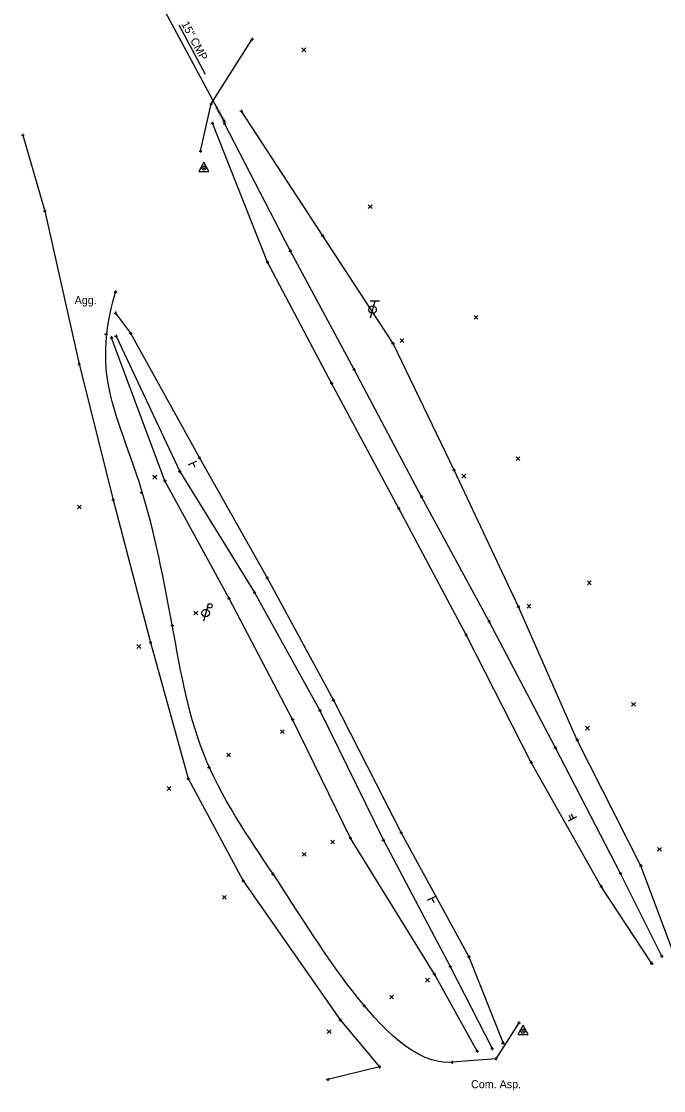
# Model space of a CAD drawing. Extents: x 2298098 to 2302860, y 557788 to 564251.
# Drawn here: x 2299513.3 to 2299738, y 561246.9 to 561620.8 of the extents above; entities that cross this region are included whole.
import ezdxf

# ---------------------------------------------------------------- set-up
doc = ezdxf.new("R2010")
doc.units = 0
for name, color, linetype in [('DR_X_Ditch', 7, 'Continuous'), ('DR_X_Elev_Flow', 7, 'Continuous'), ('DR_X_Storm_Sewer', 7, 'Continuous'), ('DR_X_Text', 7, 'Continuous'), ('PV_X_Driveway', 7, 'Continuous'), ('PV_X_Text', 7, 'Continuous'), ('SC_Scratch1', 7, 'Continuous'), ('SN_X_Public', 7, 'Continuous'), ('SV_P_Aerial_Targets', 7, 'Continuous'), ('SV_X_Break_Lines', 7, 'Continuous'), ('SV_X_Random_Point', 7, 'Continuous'), ('SV_X_Shot_Marker', 7, 'Continuous'), ('UT_X_Electric_Cells', 7, 'Continuous'), ('UT_X_Telecom_Cells', 7, 'Continuous')]:
    doc.layers.add(name, color=color, linetype=linetype)

msp = doc.modelspace()

# ---------------------------------------------------------------- linework, layer by layer
at = {"layer": 'DR_X_Ditch'}
for points in [[(2299737.31, 561293.86), (2299722.87, 561322.84), (2299700.1, 561366.76), (2299676.94, 561410.9), (2299653.32, 561454.59), (2299629.71, 561499.05), (2299607.4, 561540.48), (2299584.35, 561585.15)], [(2299546.42, 561510.69), (2299568.71, 561463.43), (2299594.86, 561421.07), (2299617.75, 561379.83), (2299639.94, 561334.43), (2299663.33, 561290.25), (2299678, 561261.57)]]:
    msp.add_lwpolyline(points, dxfattribs=at)
at = {"layer": 'DR_X_Elev_Flow'}
for p, q in [((2299583.77, 561585.83), (2299584.77, 561585.83)), ((2299584.27, 561586.33), (2299584.27, 561585.33)), ((2299584.27, 561585.83), (2299584.27, 561585.83))]:
    msp.add_line(p, q, dxfattribs=at)
at = {"layer": 'DR_X_Storm_Sewer'}
msp.add_line((2299556.47, 561637.55), (2299584.27, 561585.83), dxfattribs=at)
at = {"layer": 'DR_X_Text'}
msp.add_line((2299577.72, 561602.29), (2299568.48, 561619.48), dxfattribs=at)
at = {"layer": 'PV_X_Driveway'}
for p, q in [((2299687.34, 561270.58), (2299679.27, 561258.05)), ((2299679.27, 561258.05), (2299663.94, 561256.81))]:
    msp.add_line(p, q, dxfattribs=at)
for points in [[(2299575.95, 561575.41), (2299579.72, 561591.96), (2299594.02, 561614.57)], [(2299513.82, 561581.04), (2299521.51, 561554.48), (2299533.54, 561500.96), (2299545.43, 561453.46), (2299558.48, 561403.61), (2299571.66, 561356), (2299590.93, 561320.27), (2299624.87, 561271.61), (2299638.56, 561255.18), (2299620.47, 561250.79)]]:
    msp.add_lwpolyline(points, dxfattribs=at)
msp.add_open_spline([(2299663.94, 561256.81), (2299651.33, 561255.78), (2299626.4, 561282.53), (2299604.55, 561318.9), (2299574.6, 561360.95), (2299566.43, 561408.72), (2299556.71, 561458.84), (2299538.76, 561497.94), (2299544.69, 561521.26), (2299546.28, 561526.19)], degree=3, dxfattribs=at)
at = {"layer": 'SN_X_Public'}
for p, q in [((2299571.81, 561465.72), (2299574.66, 561467.17)), ((2299573.24, 561466.45), (2299573.96, 561465.02)), ((2299707.44, 561342.62), (2299704.61, 561341.13)), ((2299705.6, 561341.65), (2299704.86, 561343.07)), ((2299706.45, 561342.1), (2299705.71, 561343.51)), ((2299706.03, 561341.88), (2299706.03, 561341.88)), ((2299655.4, 561313.48), (2299658.29, 561314.85)), ((2299656.84, 561314.17), (2299657.53, 561312.72))]:
    msp.add_line(p, q, dxfattribs=at)
at = {"layer": 'SV_P_Aerial_Targets'}
for points in [[(2299575.34, 561568.34), (2299578.94, 561568.34), (2299577.14, 561571.56)], [(2299686.98, 561266.52), (2299690.58, 561266.52), (2299688.78, 561269.74)]]:
    msp.add_lwpolyline(points, close=True, dxfattribs=at)
for centre, radius in [((2299577.14, 561569.49), 0.7), ((2299577.14, 561569.49), 0.16), ((2299688.78, 561267.68), 0.7), ((2299688.78, 561267.68), 0.16)]:
    msp.add_circle(centre, radius, dxfattribs=at)
at = {"layer": 'SV_X_Break_Lines'}
for points in [[(2299742.16, 561293.21), (2299730.03, 561325.53), (2299707.75, 561369.5), (2299687.14, 561416.12), (2299664.66, 561463.85), (2299643.3, 561508.16), (2299618.73, 561545.83), (2299590.25, 561589.38)], [(2299733.8, 561291.39), (2299716.16, 561318.33), (2299691.63, 561361.68), (2299668.9, 561406.25), (2299645.33, 561450.44), (2299621.83, 561494.34), (2299599.4, 561536.58), (2299580.12, 561585.2)], [(2299546.23, 561518.82), (2299551.51, 561511.74), (2299575.58, 561468.14), (2299599.3, 561426.17), (2299622.44, 561383.41), (2299646.14, 561337.05), (2299669.87, 561293.72), (2299681.8, 561263.53)], [(2299672.78, 561260.7), (2299657.77, 561287.57), (2299628.41, 561335.16), (2299608.18, 561376.64), (2299585.94, 561418.99), (2299563.52, 561460.16), (2299544.89, 561510.17)]]:
    msp.add_lwpolyline(points, dxfattribs=at)
at = {"layer": 'SV_X_Random_Point'}
for p, q in [((2299611.44, 561610.2), (2299612.77, 561611.53)), ((2299611.44, 561611.53), (2299612.77, 561610.2)), ((2299634.62, 561555.36), (2299635.96, 561556.7)), ((2299634.62, 561556.7), (2299635.96, 561555.36)), ((2299671.63, 561516.67), (2299672.96, 561518.01)), ((2299671.63, 561518.01), (2299672.96, 561516.67)), ((2299645.8, 561508.48), (2299647.13, 561509.82)), ((2299645.8, 561509.82), (2299647.13, 561508.48)), ((2299686.38, 561467.2), (2299687.71, 561468.54)), ((2299686.38, 561468.54), (2299687.71, 561467.2)), ((2299559.32, 561460.75), (2299560.65, 561462.09)), ((2299559.32, 561462.09), (2299560.65, 561460.75)), ((2299559.32, 561460.72), (2299560.65, 561462.05)), ((2299559.32, 561462.05), (2299560.65, 561460.72)), ((2299667.42, 561461.11), (2299668.75, 561462.45)), ((2299667.42, 561462.45), (2299668.75, 561461.11)), ((2299532.94, 561450.33), (2299534.27, 561451.66)), ((2299532.94, 561451.66), (2299534.27, 561450.33)), ((2299711.29, 561423.79), (2299712.63, 561425.12)), ((2299711.29, 561425.12), (2299712.63, 561423.79)), ((2299690.22, 561415.61), (2299691.55, 561416.95)), ((2299690.22, 561416.95), (2299691.55, 561415.61)), ((2299573.65, 561413.23), (2299574.98, 561414.56)), ((2299573.65, 561414.56), (2299574.98, 561413.23)), ((2299553.75, 561401.53), (2299555.08, 561402.86)), ((2299553.75, 561402.86), (2299555.08, 561401.53)), ((2299726.77, 561381.31), (2299728.1, 561382.64)), ((2299726.77, 561382.64), (2299728.1, 561381.31)), ((2299710.65, 561372.95), (2299711.98, 561374.29)), ((2299710.65, 561374.29), (2299711.98, 561372.95)), ((2299603.92, 561371.77), (2299605.25, 561373.1)), ((2299603.92, 561373.1), (2299605.25, 561371.77)), ((2299585.15, 561363.56), (2299586.48, 561364.9)), ((2299585.15, 561364.9), (2299586.48, 561363.56)), ((2299564.29, 561351.9), (2299565.62, 561353.23)), ((2299564.29, 561353.23), (2299565.62, 561351.9)), ((2299621.56, 561333.17), (2299622.89, 561334.5)), ((2299621.56, 561334.5), (2299622.89, 561333.17)), ((2299611.57, 561328.85), (2299612.9, 561330.18)), ((2299611.57, 561330.18), (2299612.9, 561328.85)), ((2299735.84, 561330.61), (2299737.17, 561331.95)), ((2299735.84, 561331.95), (2299737.17, 561330.61)), ((2299583.63, 561313.83), (2299584.97, 561315.17)), ((2299583.63, 561315.17), (2299584.97, 561313.83)), ((2299654.72, 561284.84), (2299656.05, 561286.17)), ((2299654.72, 561286.17), (2299656.05, 561284.84)), ((2299642.2, 561278.98), (2299643.53, 561280.31)), ((2299642.2, 561280.31), (2299643.53, 561278.98)), ((2299620.28, 561266.81), (2299621.62, 561268.15)), ((2299620.28, 561268.15), (2299621.62, 561266.81))]:
    msp.add_line(p, q, dxfattribs=at)
at = {"layer": 'SV_X_Shot_Marker'}
for p, q in [((2299593.52, 561614.57), (2299594.52, 561614.57)), ((2299594.02, 561615.07), (2299594.02, 561614.07)), ((2299594.02, 561614.57), (2299594.02, 561614.57)), ((2299579.22, 561591.96), (2299580.22, 561591.96)), ((2299579.72, 561592.46), (2299579.72, 561591.46)), ((2299579.72, 561591.96), (2299579.72, 561591.96)), ((2299589.75, 561589.38), (2299590.75, 561589.38)), ((2299590.25, 561589.88), (2299590.25, 561588.88)), ((2299590.25, 561589.38), (2299590.25, 561589.38)), ((2299579.62, 561585.2), (2299580.62, 561585.2)), ((2299580.12, 561585.7), (2299580.12, 561584.7)), ((2299580.12, 561585.2), (2299580.12, 561585.2)), ((2299583.85, 561585.15), (2299584.85, 561585.15)), ((2299584.35, 561585.65), (2299584.35, 561584.65)), ((2299584.35, 561585.15), (2299584.35, 561585.15)), ((2299513.32, 561581.04), (2299514.32, 561581.04)), ((2299513.82, 561581.54), (2299513.82, 561580.54)), ((2299513.82, 561581.04), (2299513.82, 561581.04)), ((2299575.95, 561575.91), (2299575.95, 561574.91)), ((2299575.45, 561575.41), (2299576.45, 561575.41)), ((2299575.95, 561575.41), (2299575.95, 561575.41)), ((2299521.01, 561554.48), (2299522.01, 561554.48)), ((2299521.51, 561554.98), (2299521.51, 561553.98)), ((2299521.51, 561554.48), (2299521.51, 561554.48)), ((2299618.23, 561545.83), (2299619.23, 561545.83)), ((2299618.73, 561546.33), (2299618.73, 561545.33)), ((2299618.73, 561545.83), (2299618.73, 561545.83)), ((2299606.9, 561540.48), (2299607.9, 561540.48)), ((2299607.4, 561540.98), (2299607.4, 561539.98)), ((2299607.4, 561540.48), (2299607.4, 561540.48)), ((2299598.9, 561536.58), (2299599.9, 561536.58)), ((2299599.4, 561537.08), (2299599.4, 561536.08)), ((2299599.4, 561536.58), (2299599.4, 561536.58)), ((2299545.78, 561526.19), (2299546.78, 561526.19)), ((2299546.28, 561526.69), (2299546.28, 561525.69)), ((2299546.28, 561526.19), (2299546.28, 561526.19)), ((2299545.73, 561518.82), (2299546.73, 561518.82)), ((2299546.23, 561519.32), (2299546.23, 561518.32)), ((2299546.23, 561518.82), (2299546.23, 561518.82)), ((2299551.51, 561512.24), (2299551.51, 561511.24)), ((2299542.43, 561511.39), (2299543.43, 561511.39)), ((2299542.93, 561511.89), (2299542.93, 561510.89)), ((2299542.93, 561511.39), (2299542.93, 561511.39)), ((2299544.39, 561510.17), (2299545.39, 561510.17)), ((2299544.89, 561510.67), (2299544.89, 561509.67)), ((2299544.89, 561510.17), (2299544.89, 561510.17)), ((2299545.92, 561510.69), (2299546.92, 561510.69)), ((2299546.42, 561511.19), (2299546.42, 561510.19)), ((2299546.42, 561510.69), (2299546.42, 561510.69)), ((2299551.01, 561511.74), (2299552.01, 561511.74)), ((2299551.51, 561511.74), (2299551.51, 561511.74)), ((2299643.3, 561508.66), (2299643.3, 561507.66)), ((2299642.8, 561508.16), (2299643.8, 561508.16)), ((2299643.3, 561508.16), (2299643.3, 561508.16)), ((2299533.04, 561500.96), (2299534.04, 561500.96)), ((2299533.54, 561501.46), (2299533.54, 561500.46)), ((2299533.54, 561500.96), (2299533.54, 561500.96)), ((2299629.21, 561499.05), (2299630.21, 561499.05)), ((2299629.71, 561499.55), (2299629.71, 561498.55)), ((2299629.71, 561499.05), (2299629.71, 561499.05)), ((2299621.33, 561494.34), (2299622.33, 561494.34)), ((2299621.83, 561494.84), (2299621.83, 561493.84)), ((2299621.83, 561494.34), (2299621.83, 561494.34)), ((2299575.08, 561468.14), (2299576.08, 561468.14)), ((2299575.58, 561468.64), (2299575.58, 561467.64)), ((2299575.58, 561468.14), (2299575.58, 561468.14)), ((2299568.71, 561463.93), (2299568.71, 561462.93)), ((2299664.16, 561463.85), (2299665.16, 561463.85)), ((2299664.66, 561464.35), (2299664.66, 561463.35)), ((2299664.66, 561463.85), (2299664.66, 561463.85)), ((2299563.02, 561460.16), (2299564.02, 561460.16)), ((2299563.52, 561460.66), (2299563.52, 561459.66)), ((2299563.52, 561460.16), (2299563.52, 561460.16)), ((2299568.21, 561463.43), (2299569.21, 561463.43)), ((2299568.71, 561463.43), (2299568.71, 561463.43)), ((2299554.85, 561456.08), (2299555.85, 561456.08)), ((2299555.35, 561456.58), (2299555.35, 561455.58)), ((2299555.35, 561456.08), (2299555.35, 561456.08)), ((2299544.93, 561453.46), (2299545.93, 561453.46)), ((2299545.43, 561453.96), (2299545.43, 561452.96)), ((2299545.43, 561453.46), (2299545.43, 561453.46)), ((2299652.82, 561454.59), (2299653.82, 561454.59)), ((2299653.32, 561455.09), (2299653.32, 561454.09)), ((2299653.32, 561454.59), (2299653.32, 561454.59)), ((2299644.83, 561450.44), (2299645.83, 561450.44)), ((2299645.33, 561450.94), (2299645.33, 561449.94)), ((2299645.33, 561450.44), (2299645.33, 561450.44)), ((2299598.8, 561426.17), (2299599.8, 561426.17)), ((2299599.3, 561426.67), (2299599.3, 561425.67)), ((2299599.3, 561426.17), (2299599.3, 561426.17)), ((2299585.44, 561418.99), (2299586.44, 561418.99)), ((2299585.94, 561419.49), (2299585.94, 561418.49)), ((2299585.94, 561418.99), (2299585.94, 561418.99)), ((2299594.36, 561421.07), (2299595.36, 561421.07)), ((2299594.86, 561421.57), (2299594.86, 561420.57)), ((2299594.86, 561421.07), (2299594.86, 561421.07)), ((2299686.64, 561416.12), (2299687.64, 561416.12)), ((2299687.14, 561416.62), (2299687.14, 561415.62)), ((2299687.14, 561416.12), (2299687.14, 561416.12)), ((2299676.94, 561411.4), (2299676.94, 561410.4)), ((2299565.6, 561409.51), (2299566.6, 561409.51)), ((2299566.1, 561410.01), (2299566.1, 561409.01)), ((2299566.1, 561409.51), (2299566.1, 561409.51)), ((2299676.44, 561410.9), (2299677.44, 561410.9)), ((2299676.94, 561410.9), (2299676.94, 561410.9)), ((2299558.48, 561404.11), (2299558.48, 561403.11)), ((2299668.4, 561406.25), (2299669.4, 561406.25)), ((2299668.9, 561406.75), (2299668.9, 561405.75)), ((2299668.9, 561406.25), (2299668.9, 561406.25)), ((2299557.98, 561403.61), (2299558.98, 561403.61)), ((2299558.48, 561403.61), (2299558.48, 561403.61)), ((2299621.94, 561383.41), (2299622.94, 561383.41)), ((2299622.44, 561383.91), (2299622.44, 561382.91)), ((2299622.44, 561383.41), (2299622.44, 561383.41)), ((2299617.25, 561379.83), (2299618.25, 561379.83)), ((2299617.75, 561380.33), (2299617.75, 561379.33)), ((2299617.75, 561379.83), (2299617.75, 561379.83)), ((2299607.68, 561376.64), (2299608.68, 561376.64)), ((2299608.18, 561377.14), (2299608.18, 561376.14)), ((2299608.18, 561376.64), (2299608.18, 561376.64)), ((2299699.6, 561366.76), (2299700.6, 561366.76)), ((2299700.1, 561367.26), (2299700.1, 561366.26)), ((2299700.1, 561366.76), (2299700.1, 561366.76)), ((2299707.25, 561369.5), (2299708.25, 561369.5)), ((2299707.75, 561370), (2299707.75, 561369)), ((2299707.75, 561369.5), (2299707.75, 561369.5)), ((2299578.45, 561359.93), (2299579.45, 561359.93)), ((2299578.95, 561360.43), (2299578.95, 561359.43)), ((2299578.95, 561359.93), (2299578.95, 561359.93)), ((2299691.13, 561361.68), (2299692.13, 561361.68)), ((2299691.63, 561362.18), (2299691.63, 561361.18)), ((2299691.63, 561361.68), (2299691.63, 561361.68)), ((2299571.16, 561356), (2299572.16, 561356)), ((2299571.66, 561356.5), (2299571.66, 561355.5)), ((2299571.66, 561356), (2299571.66, 561356)), ((2299645.64, 561337.05), (2299646.64, 561337.05)), ((2299646.14, 561337.55), (2299646.14, 561336.55)), ((2299646.14, 561337.05), (2299646.14, 561337.05)), ((2299627.91, 561335.16), (2299628.91, 561335.16)), ((2299628.41, 561335.66), (2299628.41, 561334.66)), ((2299628.41, 561335.16), (2299628.41, 561335.16)), ((2299639.44, 561334.43), (2299640.44, 561334.43)), ((2299639.94, 561334.93), (2299639.94, 561333.93)), ((2299639.94, 561334.43), (2299639.94, 561334.43)), ((2299729.53, 561325.53), (2299730.53, 561325.53)), ((2299730.03, 561326.03), (2299730.03, 561325.03)), ((2299730.03, 561325.53), (2299730.03, 561325.53)), ((2299600.81, 561322.64), (2299601.81, 561322.64)), ((2299601.31, 561323.14), (2299601.31, 561322.14)), ((2299601.31, 561322.64), (2299601.31, 561322.64)), ((2299722.37, 561322.84), (2299723.37, 561322.84)), ((2299722.87, 561323.34), (2299722.87, 561322.34)), ((2299722.87, 561322.84), (2299722.87, 561322.84)), ((2299590.43, 561320.27), (2299591.43, 561320.27)), ((2299590.93, 561320.77), (2299590.93, 561319.77)), ((2299590.93, 561320.27), (2299590.93, 561320.27)), ((2299715.66, 561318.33), (2299716.66, 561318.33)), ((2299716.16, 561318.83), (2299716.16, 561317.83)), ((2299716.16, 561318.33), (2299716.16, 561318.33)), ((2299669.37, 561293.72), (2299670.37, 561293.72)), ((2299669.87, 561294.22), (2299669.87, 561293.22)), ((2299669.87, 561293.72), (2299669.87, 561293.72)), ((2299733.8, 561291.89), (2299733.8, 561290.89)), ((2299736.81, 561293.86), (2299737.81, 561293.86)), ((2299737.31, 561294.36), (2299737.31, 561293.36)), ((2299737.31, 561293.86), (2299737.31, 561293.86)), ((2299657.77, 561288.07), (2299657.77, 561287.07)), ((2299662.83, 561290.25), (2299663.83, 561290.25)), ((2299663.33, 561290.75), (2299663.33, 561289.75)), ((2299663.33, 561290.25), (2299663.33, 561290.25)), ((2299733.3, 561291.39), (2299734.3, 561291.39)), ((2299733.8, 561291.39), (2299733.8, 561291.39)), ((2299657.27, 561287.57), (2299658.27, 561287.57)), ((2299657.77, 561287.57), (2299657.77, 561287.57)), ((2299633.26, 561277.03), (2299633.26, 561276.03)), ((2299632.76, 561276.53), (2299633.76, 561276.53)), ((2299633.26, 561276.53), (2299633.26, 561276.53)), ((2299624.37, 561271.61), (2299625.37, 561271.61)), ((2299624.87, 561272.11), (2299624.87, 561271.11)), ((2299624.87, 561271.61), (2299624.87, 561271.61)), ((2299686.84, 561270.58), (2299687.84, 561270.58)), ((2299687.34, 561271.08), (2299687.34, 561270.08)), ((2299687.34, 561270.58), (2299687.34, 561270.58)), ((2299678, 561262.07), (2299678, 561261.07)), ((2299681.3, 561263.53), (2299682.3, 561263.53)), ((2299681.8, 561264.03), (2299681.8, 561263.03)), ((2299681.8, 561263.53), (2299681.8, 561263.53)), ((2299672.28, 561260.7), (2299673.28, 561260.7)), ((2299672.78, 561261.2), (2299672.78, 561260.2)), ((2299672.78, 561260.7), (2299672.78, 561260.7)), ((2299677.5, 561261.57), (2299678.5, 561261.57)), ((2299678, 561261.57), (2299678, 561261.57)), ((2299678.77, 561258.05), (2299679.77, 561258.05)), ((2299679.27, 561258.55), (2299679.27, 561257.55)), ((2299679.27, 561258.05), (2299679.27, 561258.05)), ((2299638.06, 561255.18), (2299639.06, 561255.18)), ((2299638.56, 561255.68), (2299638.56, 561254.68)), ((2299638.56, 561255.18), (2299638.56, 561255.18)), ((2299663.44, 561256.81), (2299664.44, 561256.81)), ((2299663.94, 561257.31), (2299663.94, 561256.31)), ((2299663.94, 561256.81), (2299663.94, 561256.81)), ((2299619.97, 561250.79), (2299620.97, 561250.79)), ((2299620.47, 561251.29), (2299620.47, 561250.29)), ((2299620.47, 561250.79), (2299620.47, 561250.79))]:
    msp.add_line(p, q, dxfattribs=at)
at = {"layer": 'UT_X_Electric_Cells'}
for p, q in [((2299578.62, 561417.09), (2299577.02, 561411.09)), ((2299578.28, 561415.81), (2299579.47, 561415.81)), ((2299578.62, 561417.09), (2299579.47, 561417.09))]:
    msp.add_line(p, q, dxfattribs=at)
msp.add_circle((2299577.77, 561413.89), 1.3, dxfattribs=at)
msp.add_arc((2299579.49, 561416.45), 0.638, 268.8767, 91.1233, dxfattribs=at)
at = {"layer": 'UT_X_Telecom_Cells'}
for p, q in [((2299638.56, 561522.99), (2299635.36, 561522.99)), ((2299636.96, 561522.99), (2299635.36, 561516.99))]:
    msp.add_line(p, q, dxfattribs=at)
msp.add_circle((2299636.16, 561519.99), 1.3, dxfattribs=at)

# ---------------------------------------------------------------- texts
at = {"layer": 'DR_X_Text'}
msp.add_text('15" CMP', height=2.8, rotation=298.2548, dxfattribs=at).set_placement((2299569.18, 561619.93))
at = {"layer": 'PV_X_Text'}
for s, p in [('Agg.', (2299531.96, 561521.93)), ('Com. Asp.', (2299670.61, 561247.74))]:
    msp.add_text(s, height=2.8, dxfattribs=at).set_placement(p)
at = {"layer": 'SC_Scratch1'}
msp.add_text("1,136.96'", height=1, rotation=298.2548, dxfattribs=at).set_placement((2299581.09, 561590.7))

doc.saveas('drawing.dxf')
